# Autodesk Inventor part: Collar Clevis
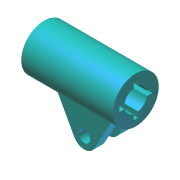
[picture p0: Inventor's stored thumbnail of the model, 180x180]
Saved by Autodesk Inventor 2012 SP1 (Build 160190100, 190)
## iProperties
Shininess: 64.0
Angle Display Precision: 2
Document Length Units: 11272
Document Angle Units: 11279
Document Time Units: 11290
Document Mass Units: 11286
Document Length Units Precision: 3
Document Angle Units Precision: 2
Created: 2008-04
Material: Steel, Mild
Document SubType Name: Modeling
Density: 7.86 g/cm^3
Mass: 165.667 g
Surface Area: 94.2493 cm^2
Volume: 21.0772 cm^3
Part Number: Collar Clevis
Density: 7.75
Volumn: 19.796899718527946
Area: 75.95780474593748
PropertySet Name: Model Information
Control State: 0
Master: False
Checked Out: False
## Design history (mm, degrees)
sketch "Sketch1"
  geometry: L1 (25.4, 0)-(25.4, 12.7); L2 (25.4, 12.7)-(-25.4, 12.7); L3 (-25.4, 12.7)-(-25.4, 0); L4 (25.4, 0)-(-25.4, 0); L5 (25.4, 0)-(-25.4, 0)
  constraints: 10 end point, 2 horizontal, 2 vertical, 1 other
  dimensions: "d1" = 50.8 distance of L1.end L2.end; "d56" = 25.4 diameter of L2 L4
revolve "RevolutionAngle1" sketch "Sketch1" stored, may be unused: angle "d4" = 360 deg
sketch "Sketch21"
  geometry: L1 (22.225, 0)-(22.225, 6.35); L2 (22.225, 6.35)-(11.927, 25.262); L3 (0.773, 25.262)-(-9.525, 6.35); L4 (-9.525, 6.35)-(-9.525, 0); L5 (-9.525, 0)-(22.225, 0); L6 (25.4, -12.7)-(25.4, 12.7) reference; A1 r 6.35 centre (6.35, 22.225) between (11.927, 25.262) and (0.773, 25.262); 1 further point
  constraints: 10 end point, 2 point on circle, 2 tangent, 1 centre point, 1 horizontal alignment, 1 parallel, 1 perpendicular, 1 point on line, 1 vertical
  dimensions: "d64" = 6.35 radius of A1; "d65" = 19.05 distance from line of L6 A1.centre; "d66" = 31.75 distance between parallel lines of L4 L1; "d67" = 15.875 distance from line of A1.centre L1 (= 0.5 x d66); "d68" = 22.225 vertical distance of point (0, 0) A1.centre; "d69" = 6.35 distance of L1.start L1.end
extrude "Extrusion14" join sketch "Sketch21" stored distance "d70" = 19.05; taper "d71" = 0 deg
sketch "Sketch22"
  geometry: L1 (12.7, 3.81)-(28.575, 3.81); L2 (28.575, 3.81)-(28.575, -3.81); L3 (28.575, -3.81)-(12.7, -3.81); L4 (12.7, -3.81)-(12.7, 3.81); L5 (28.575, -9.525)-(28.575, 9.525) reference; 1 further point
  constraints: 8 end point, 2 parallel, 1 collinear, 1 horizontal, 1 perpendicular
  dimensions: "d72" = 7.62 distance of L3.end L1.start; "d73" = 3.81 distance from line of L1 point (0, 0) (= 0.5 x d72); "d74" = 12.7 distance from line of point (0, 0) L4
extrude "Extrusion15" cut sketch "Sketch22" stored distance "d75" = 19.05; taper "d76" = 0 deg
hole "Hole2" diameter "d79" = 6.35; stored, may be unused: countersink angle "d83" = 82 deg, drill point angle "d85" = 118 deg; dims "d77" = 25.4, "d78" = 25.4, "d80" = 19.05, "d81" = 9.525, "d82" = 6.35, "d84" = 25.4
sketch "Sketch2"
  geometry: C1 r 12.7 at (0, 0) reference; 1 further point
hole "Hole1" sketch "Sketch2" at (0, 0) diameter "d6" = 12.7; stored, may be unused: countersink angle "d10" = 82 deg, drill point angle "d12" = 118 deg; dims "d7" = 12.7, "d8" = 9.525, "d9" = 6.35, "d11" = 19.05
sketch "Sketch4"
  geometry: L1 (5.334, 1.27)-(5.334, -1.27); L2 (9.144, 1.27)-(5.334, 1.27); L3 (9.144, -1.27)-(9.144, 1.27); L4 (5.334, -1.27)-(9.144, -1.27); C1 r 6.35 at (0, 0) reference
  constraints: 8 end point, 2 perpendicular
  dimensions: "d18" = 2.54 distance of L3.start L2.start; "d20" = 3.81 distance of L2.start L1.start; "d22" = 5.334 horizontal distance of L1.end C1.centre; "d52" = 1.27 distance from line of C1.centre L2 (= 0.5 x d18)
extrude "ExtrusionThru1" cut sketch "Sketch4" stored distance "d23" = 3.302; taper "d24" = 0 deg
pattern_circular "Circular Pattern2" dims angle "d54" = 360 deg
fillet "Fillet3" dims "d88" = 1.524
body "Solid1"
other parameters: "d0" = 50.8 (derived), "d2" = 12.7 (derived), "d5" = 0, "d13" = 6.35 (derived), "d17" = 2.54 (derived), "d19" = 3.81 (derived), "d21" = 5.334 (derived)
